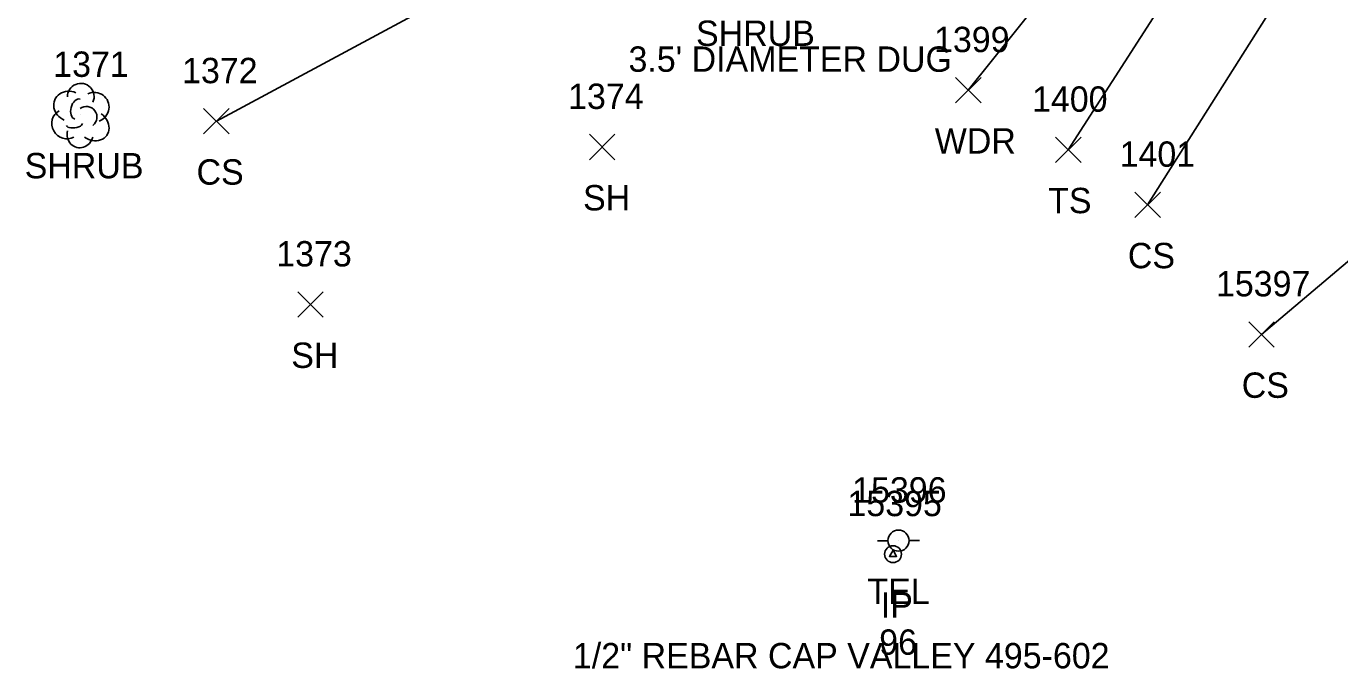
# Model space of a CAD drawing. Extents: x 1606530 to 1613020, y 784959 to 789666.
# Drawn here: x 1608956.3 to 1609059.8, y 788247 to 788297.7 of the extents above; entities that cross this region are included whole.
import ezdxf

# ---------------------------------------------------------------- set-up
doc = ezdxf.new("R2010")
doc.units = 0
for name, color, linetype in [('L_A', 7, 'Continuous'), ('L_I', 7, 'Continuous'), ('L_TIC', 7, 'Continuous'), ('LAWA', 7, 'Continuous'), ('LELB', 7, 'Continuous'), ('LSH', 7, 'Continuous'), ('M_A', 7, 'Continuous'), ('M_C', 7, 'Continuous'), ('M_I', 7, 'Continuous'), ('MPIR', 7, 'Continuous'), ('U_A', 7, 'Continuous'), ('U_C', 7, 'Continuous'), ('U_I', 7, 'Continuous'), ('UP', 7, 'Continuous')]:
    doc.layers.add(name, color=color, linetype=linetype)

msp = doc.modelspace()

# ---------------------------------------------------------------- linework, layer by layer
at = {"layer": 'L_TIC'}
for points in [[(1609029.56, 788291.64), (1609031.56, 788293.64)], [(1609031.56, 788291.64), (1609029.56, 788293.64)], [(1608970.32, 788289.19), (1608972.32, 788291.19)], [(1608972.32, 788289.19), (1608970.32, 788291.19)], [(1609000.72, 788287.16), (1609002.72, 788289.16)], [(1609002.72, 788287.16), (1609000.72, 788289.16)], [(1609037.44, 788286.94), (1609039.44, 788288.94)], [(1609039.44, 788286.94), (1609037.44, 788288.94)], [(1609043.69, 788282.6), (1609045.69, 788284.6)], [(1609045.69, 788282.6), (1609043.69, 788284.6)], [(1608977.73, 788274.74), (1608979.73, 788276.74)], [(1608979.73, 788274.74), (1608977.73, 788276.74)], [(1609052.66, 788272.38), (1609054.66, 788274.38)], [(1609054.66, 788272.38), (1609052.66, 788274.38)]]:
    msp.add_lwpolyline(points, dxfattribs=at)
at = {"layer": 'LAWA'}
msp.add_lwpolyline([(1609030.56, 788292.64), (1609056.03, 788324.44), (1609082.56, 788354.61), (1609090.16, 788369.42), (1609097.26, 788381.32), (1609109.23, 788386.03), (1609115.48, 788389.16), (1609124.65, 788392.27), (1609168.82, 788397.24), (1609199.02, 788403.22), (1609247.62, 788406.18), (1609289.08, 788410.02), (1609331.31, 788409.89), (1609380.07, 788411.97), (1609422.47, 788410.64), (1609441.9, 788412.64), (1609456.94, 788393.19), (1609459.97, 788389.84), (1609451.94, 788379.3), (1609445.61, 788371.6)], dxfattribs=at)
at = {"layer": 'LELB'}
for points in [[(1609053.66, 788273.38), (1609077.55, 788293.59), (1609095.85, 788318.07), (1609115.19, 788336.22), (1609111.13, 788353.77), (1609121.97, 788374.07), (1609132.13, 788390.34), (1609178.08, 788389.18)], [(1609044.69, 788283.6), (1609058.26, 788305.11), (1609096.98, 788342.47), (1609105.85, 788363.2), (1609115.48, 788389.16)], [(1609038.44, 788287.94), (1609056.53, 788316.1), (1609093.18, 788350), (1609102.91, 788366.58), (1609109.23, 788386.03)], [(1608971.32, 788290.19), (1608998.99, 788305.09), (1609044.23, 788328.65), (1609082.56, 788354.61)]]:
    msp.add_lwpolyline(points, dxfattribs=at)
at = {"layer": 'LSH'}
msp.add_line((1608960.59, 788290.69), (1608960.59, 788290.69), dxfattribs=at)
msp.add_line((1608960.59, 788290.69), (1608960.59, 788290.69), dxfattribs=at)
msp.add_arc((1608960.64, 788292.13), 1.05, 335.5272, 180.9563, dxfattribs=at)
for centre, major_axis, ratio, start_param, end_param in [((1608959.8, 788291.36), (1.21, -0.51), 0.895232, 1.570796, 4.712389), ((1608961.64, 788291.28), (-1.14, -0.48), 0.949671, 1.570796, 4.712389), ((1608960.39, 788291.15), (-0.208, -0.792), 0.645439, 3.141593, 6.283185), ((1608961.09, 788290.53), (-0.5, 0.667), 0.989748, 3.141593, 6.283185), ((1608959.51, 788289.98), (0.58, -1.04), 0.959034, 3.141593, 6.283185), ((1608961.59, 788289.86), (-1.09, 0.79), 0.841452, 1.570796, 4.712389), ((1608960.59, 788289.19), (0.26, 1.06), 0.942809, 1.570796, 4.712389), ((1608960.14, 788289.94), (-0.625, -0.083), 0.423636, 0, 3.141593)]:
    msp.add_ellipse(centre, major_axis=major_axis, ratio=ratio, start_param=start_param, end_param=end_param, dxfattribs=at)
at = {"layer": 'MPIR'}
msp.add_lwpolyline([(1609024.63, 788256.38), (1609024.34, 788255.88), (1609024.91, 788255.88)], close=True, dxfattribs=at)
msp.add_circle((1609024.63, 788256.05), 0.667, dxfattribs=at)
at = {"layer": 'UP'}
for p, q in [((1609023.4, 788257.11), (1609024.22, 788257.11)), ((1609025.06, 788257.12), (1609025.06, 788257.12)), ((1609026.72, 788257.12), (1609025.89, 788257.12)), ((1609025.89, 788257.12), (1609025.89, 788257.12)), ((1609026.72, 788257.12), (1609026.72, 788257.12))]:
    msp.add_line(p, q, dxfattribs=at)
msp.add_circle((1609025.06, 788257.12), 0.833, dxfattribs=at)

# ---------------------------------------------------------------- texts
at = {"layer": 'L_A'}
for s, p in [('SHRUB', (1609009.11, 788296.13)), ('WDR', (1609027.92, 788287.64)), ('SHRUB', (1608956.22, 788285.69)), ('CS', (1608969.76, 788285.19)), ('SH', (1609000.21, 788283.16)), ('TS', (1609036.85, 788282.94)), ('CS', (1609043.13, 788278.6)), ('SH', (1608977.22, 788270.74)), ('CS', (1609052.1, 788268.38))]:
    msp.add_text(s, height=2, dxfattribs=at).set_placement(p)
at = {"layer": 'L_I'}
for s, p in [('1399', (1609027.86, 788295.64)), ('1371', (1608958.47, 788293.69)), ('1372', (1608968.62, 788293.19)), ('1374', (1608999.03, 788291.16)), ('1400', (1609035.58, 788290.94)), ('1401', (1609042.48, 788286.6)), ('1373', (1608976.04, 788278.74)), ('15397', (1609050.07, 788276.38))]:
    msp.add_text(s, height=2, dxfattribs=at).set_placement(p)
at = {"layer": 'M_A'}
msp.add_text('IP', height=2, dxfattribs=at).set_placement((1609023.67, 788251.05))
at = {"layer": 'M_C'}
msp.add_text('1/2" REBAR CAP VALLEY 495-602', height=2, dxfattribs=at).set_placement((1608999.41, 788247.05))
at = {"layer": 'M_I'}
msp.add_text('15395', height=2, dxfattribs=at).set_placement((1609021.04, 788259.05))
at = {"layer": 'U_A'}
msp.add_text('TEL', height=2, dxfattribs=at).set_placement((1609022.61, 788252.12))
at = {"layer": 'U_C'}
for s, p in [("3.5' DIAMETER DUG", (1609003.79, 788294.09)), ('96', (1609023.54, 788248.12))]:
    msp.add_text(s, height=2, dxfattribs=at).set_placement(p)
at = {"layer": 'U_I'}
msp.add_text('15396', height=2, dxfattribs=at).set_placement((1609021.41, 788260.12))

doc.saveas('drawing.dxf')
